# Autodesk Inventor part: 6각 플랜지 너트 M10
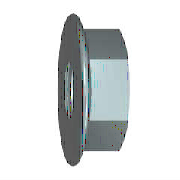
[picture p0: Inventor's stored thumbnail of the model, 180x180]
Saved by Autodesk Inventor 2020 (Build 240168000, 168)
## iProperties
Created: 2012-02
Part Number: 6각 플랜지 너트 M10
Material: 강철, 연강
Description: 플랜지붙이 6각 너트
Document SubType Name: Modeling
Standard: JIS B 1190
Designer: mdu-01
Standards Organization: JIS
Language: ko-KR
Size Designation: M 10
Categories: <MemberInstance><Categories><Category DisplayName="조임쇠" InternalName="e4da775c-781d-43d5-af7c-5136215cf5a6" Mnemonic="FSTN"><Category DisplayName="너트" InternalN
Density: 1 g/cm^3
Appearance: 강철
IsCustomPart: 1
Author: mdu-01
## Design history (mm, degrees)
sketch "스케치1"
  geometry: L1 (-2.276, 0)-(12.046, 0) reference; L2 (3.914, 7)-(2.239, 9.9); L3 (3.914, 7)-(10, 7); L4 (10, 7)-(10, 0); L5 (3.914, 7)-(3.914, 0); L6 (0, -2.152)-(0, 12.911) reference; A1 r 1.2 centre (1.2, 9.3) between (2.239, 9.9) and (0, 9.3); 1 further point
  constraints: 8 end point, 3 point on line, 2 perpendicular, 2 point on circle, 2 tangent, 1 centre point, 1 parallel
  dimensions: "d2" = 14 diameter of L3 L1 (= SW); "d4" = 21 dimension on A1 L1 (= LADI); "d5" = 1.2 radius of A1 (= PHH); "d15" = 10 distance between parallel lines of L4 L6 (= KOH); "d16" = 30 deg angle of L6 L2 (= KEWI)
revolve "링" sketch "스케치1" stored, may be unused: angle "d8" = 90 deg
sketch "스케치2"
  geometry: L1 (-7, -4.041)-(-7, 4.041); L2 (-7, 4.041)-(0, 8.083); L3 (0, 8.083)-(7, 4.041); L4 (7, 4.041)-(7, -4.041); L5 (7, -4.041)-(0, -8.083); L6 (0, -8.083)-(-7, -4.041); C1 r 4.9 at (0, 0); C2 r 9.3 at (0, 0) reference; 1 further point
  constraints: 12 end point, 1 centre point, 1 coincident, 1 vertical, 11 other
  dimensions: "d6" = 16.16581 distance of L5.end L2.end (= 1.1547 x SW)
extrude "본체" join sketch "스케치2" distance "d7" = 10 (= KOH); taper "d9" = 0 deg
sketch "스케치3"
  geometry: L1 (3.288, 8.083)-(10, 8.083) reference; L2 (10, 4.041)-(10, 8.083) reference; L3 (0, -9.3)-(0, 9.3) reference; L4 (-2, 0)-(12, 0) reference; L5 (9.375, 8.083)-(10, 7)
  constraints: 2 end point, 2 point on line
  dimensions: "d10" = 30 deg angle of L2 L5 (= ANG1); "d11" = 14 diameter of L5.end L4 (= SW0)
revolve "모따기1" sketch "스케치3" stored, may be unused: angle "d24" = 90 deg
sketch "스케치4"
  geometry: C1 r 9.3 at (0, 0) reference; 1 further point
  constraints: 1 coincident
hole "스레드" sketch "스케치4" at (0, 0) diameter "d25" = 8.376; stored, may be unused: countersink angle "d29" = 82 deg, drill point angle "d31" = 118 deg; dims "d26" = 6, "d27" = 4, "d28" = 2, "d30" = 8
workaxis "Work Axis1"
workplane "Work Plane1"
body "Solid1"
chamfer "모따기2" distance "d12" = 0.8119 (= -0.5 x GD1 + 0.5 x NND); stored, may be unused: angle "d13" = 30 deg, second distance "d46" = 0.8119 (= -0.5 x GD1 + 0.5 x NND)
chamfer "모따기3" distance "d51" = 0.8119 (= -0.5 x GD1 + 0.5 x NND); stored, may be unused: second distance "d52" = 2, angle "d53" = 45 deg
other parameters: "ANG1" = 30 deg [user parameter; used in 1 equation term], "KEWI" = 30 deg [user parameter; used in 1 equation term], "LADI" = 21 [user parameter; used in 2 equation terms], "SW" = 14 [user parameter; used in 3 equation terms], "PHH" = 1.2 [user parameter; used in 2 equation terms], "KOH" = 10 [user parameter; used in 2 equation terms], "SW0" = 14 [user parameter; used in 1 equation term], "GD1" = 8.3762 (computed from THREADDIA, PTC, TOA) [user parameter; used in 3 equation terms], "d1" = 21 (= LADI), "d3" = 1.2 (= PHH), "d45" = 0, "d47" = 0, "d49" = 0, "d54" = 0, "GUL" = 0.8119 (= 0.541266 x PTC) [user parameter], "TPU" = 6.66667 (computed from PTC) [user parameter], "RR" = 1.4 [user parameter], "TOA" = 30 deg [user parameter; used in 1 equation term], "PTC" = 1.5 [user parameter; used in 4 equation terms], "GAL" = 0.8119 (= 0.541266 x PTC) [user parameter], "E0" = 16.17 (= 1.155 x SW) [user parameter]
